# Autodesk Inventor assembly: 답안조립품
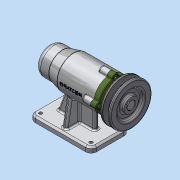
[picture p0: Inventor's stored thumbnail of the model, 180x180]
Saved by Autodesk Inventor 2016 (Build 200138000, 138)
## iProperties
Created: 2019-07
Part Number: 답안조립품
Material: 일반
Document SubType Name: Assembly
Designer: Administrator
Author: Administrator
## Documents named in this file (12)
- C:\Users\Administrator\Desktop\490704V1009\답안조립품.iam
- C:\Users\Administrator\Desktop\490704V1009\본체.ipt
- C:\Users\Administrator\Desktop\490704V1009\베어링 6004.ipt
- C:\Users\Administrator\Desktop\490704V1009\베어링 51202.ipt
- C:\Users\Administrator\Desktop\490704V1009\어댑터슬리브.ipt
- C:\Users\Administrator\Desktop\490704V1009\축.ipt
- C:\Users\Administrator\Desktop\490704V1009\볼트 M4.ipt
- C:\Users\Administrator\Desktop\490704V1009\커버.ipt
- C:\Users\Administrator\Desktop\490704V1009\키 5 x 5 x 16.ipt
- C:\Users\Administrator\Desktop\490704V1009\V벨트풀리.ipt
- C:\Users\Administrator\Desktop\490704V1009\멈춤나사 M3.ipt
- C:\Users\Administrator\Desktop\490704V1009\오일 실.ipt
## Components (1 placed, 1 different names)
1. V벨트풀리:1
